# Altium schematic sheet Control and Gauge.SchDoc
size 431 x 279 mm; Date: Not shown in title block; ApprovedBy: Not shown in title block; CheckedBy: Not shown in title block; Author: Not shown in title block; CompanyName: Not shown in title block; Engineer: Not shown in title block; Organization: Not shown in title block; Address1: Not shown in title block; Address2: Not shown in title block; Address3: Not shown in title block; Address4: Not shown in title block; DocumentNumber: 1; Revision: Use project parameter SCH_Rev; SheetNumber: 2; SheetTotal: 3; PageSetup: Record=PageOptions¦CenterHorizontal=True¦CenterVertical=True¦PrintScale=1.00¦XCorrection=1.00¦YCorrection=1.00¦PrintKind=0¦BorderSize=5000000¦LeftOffset=0¦BottomOffset=0¦Orientation=2¦PaperLength=1000¦PaperWidth=1000¦Scale=100¦PaperSource=15¦PrintQuality=600¦MediaType=1¦DitherType=10¦PaperKind=Letter¦PrintScaleMode=1
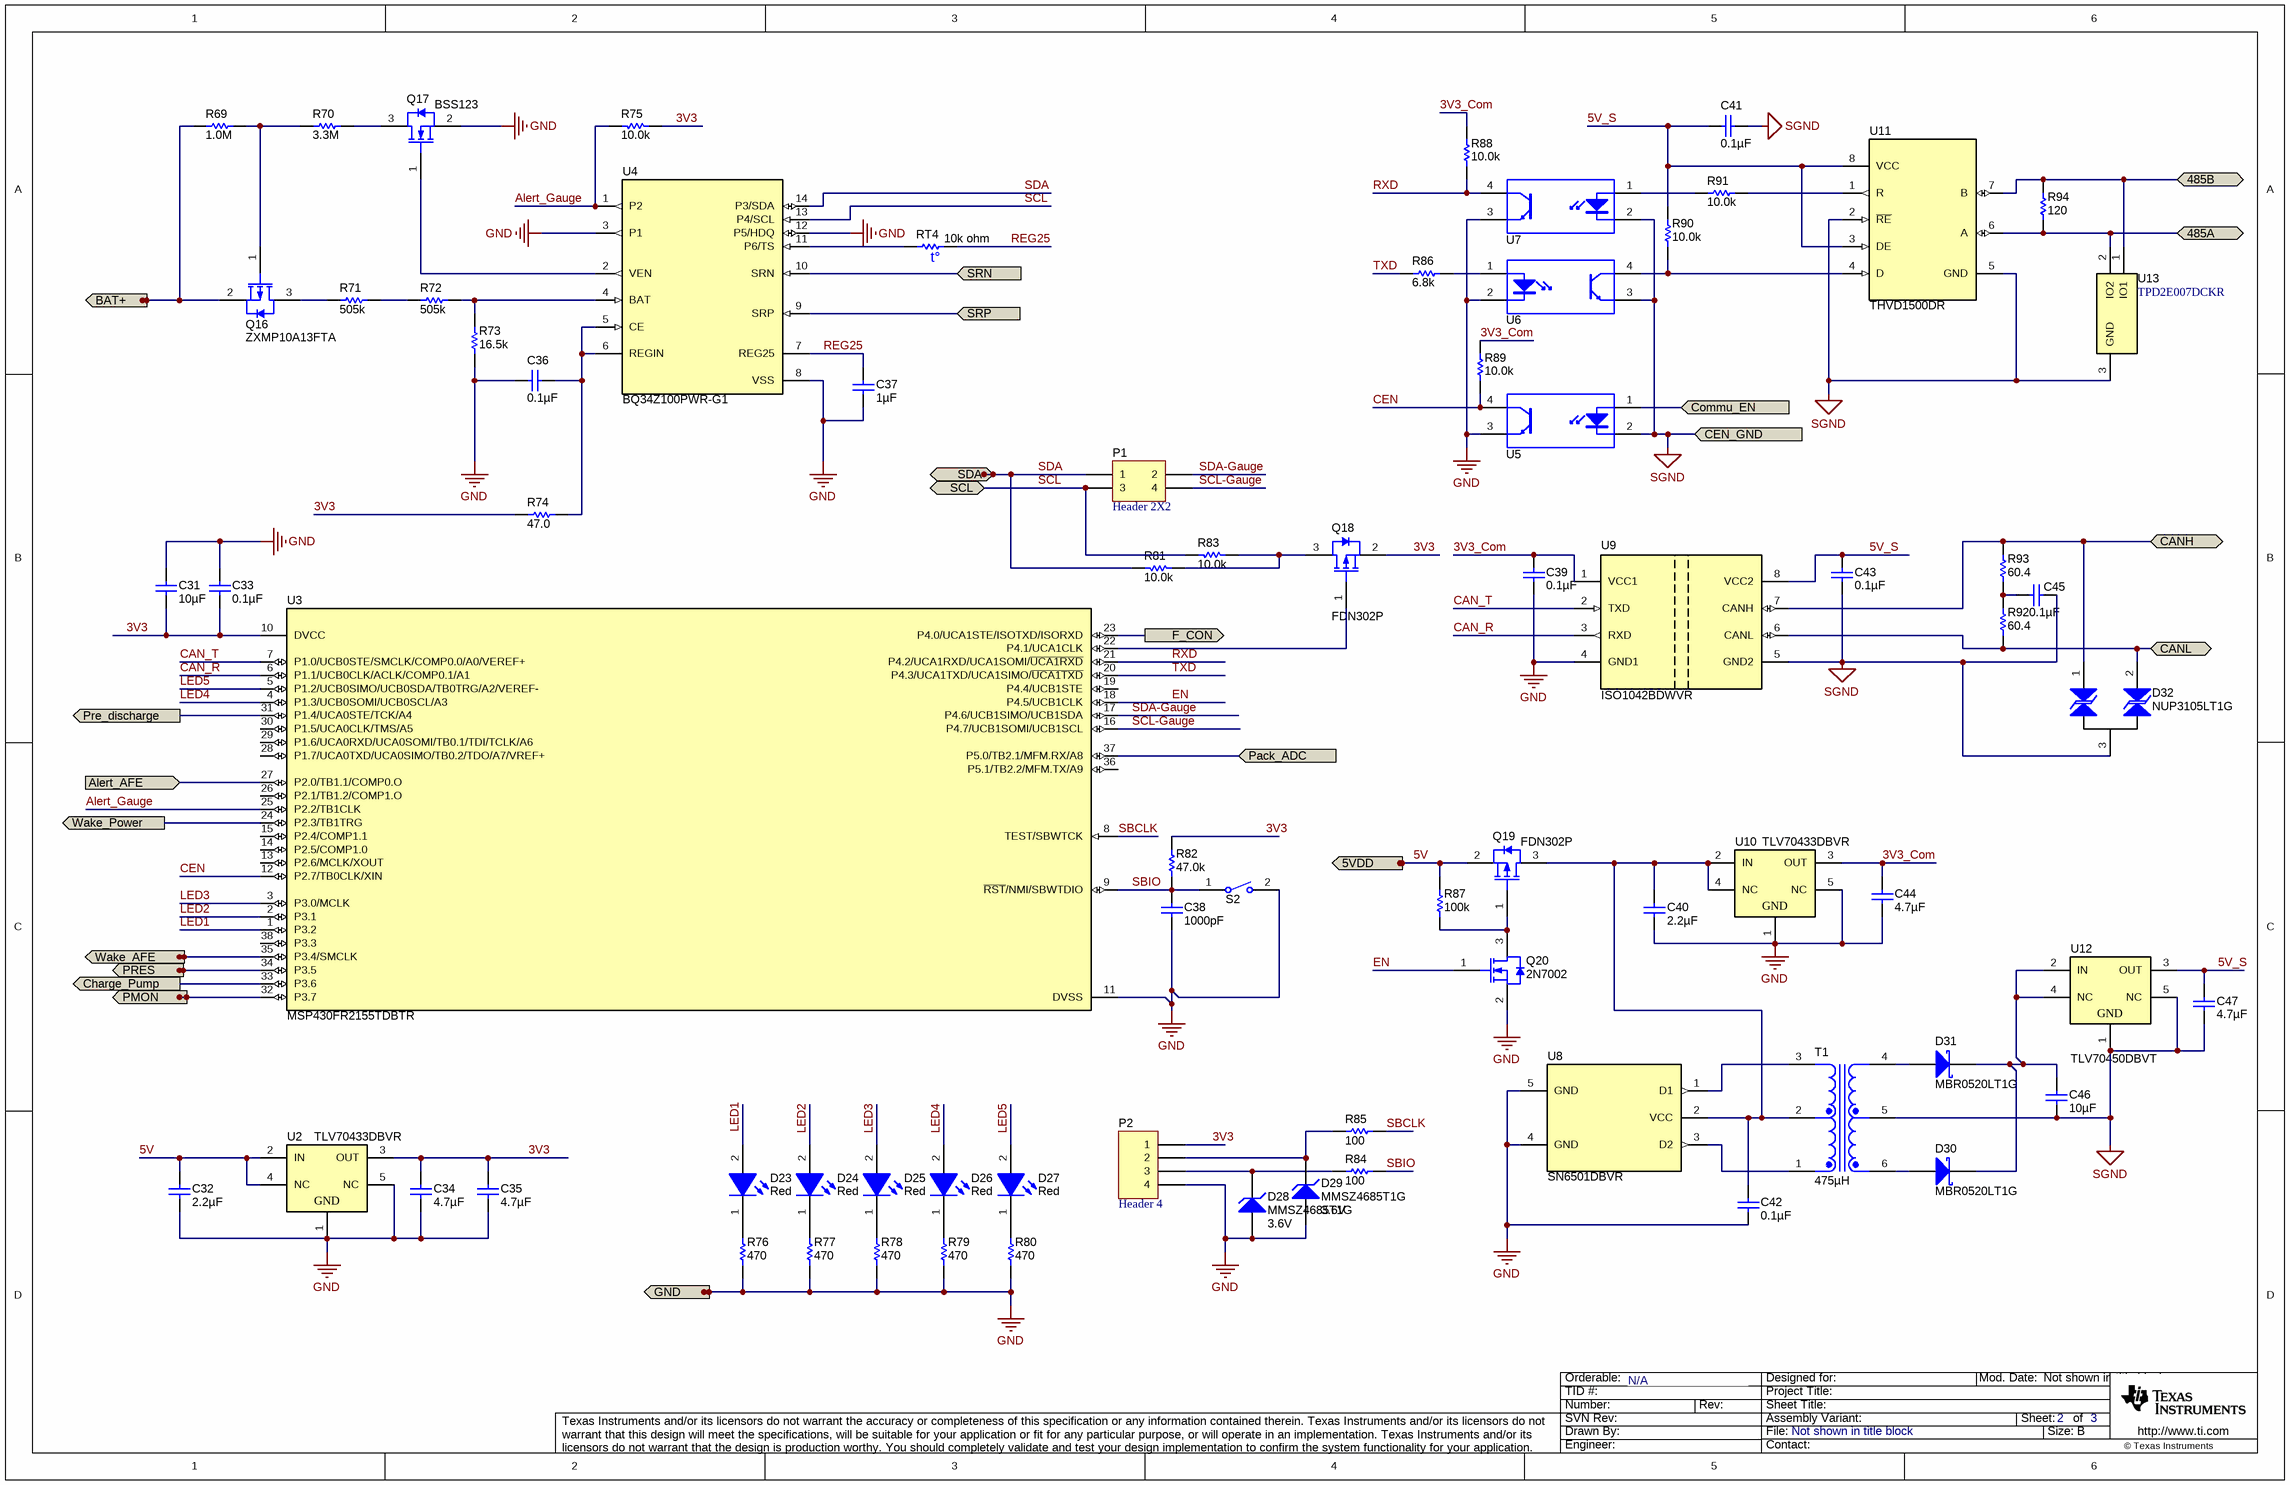
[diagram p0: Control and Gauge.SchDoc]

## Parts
C31  ValueDisplayed: 10µF  [0805_HV]  (hidden comment: CL21B106KOQNNNE)
C32  ValueDisplayed: 2.2µF  [0603]  (hidden comment: GRM188R71A225KE15D)
C33  ValueDisplayed: 0.1µF  [0603]  (hidden comment: GRM188R71C104KA01D)
C34  ValueDisplayed: 4.7µF  [0603]  (hidden comment: GRM188R61C475KAAJ)
C35  ValueDisplayed: 4.7µF  [0603]  (hidden comment: GRM188R61C475KAAJ)
C36  ValueDisplayed: 0.1µF  [0603]  (hidden comment: GRM188R71H104KA93D)
C37  ValueDisplayed: 1µF  [0603]  (hidden comment: GRM188R71C105KE15D)
C38  ValueDisplayed: 1000pF  [0603S]  (hidden comment: GRM1885C1H102JA01D)
C39  ValueDisplayed: 0.1µF  [0603]  (hidden comment: GRM188R71C104KA01D)
C40  ValueDisplayed: 2.2µF  [0603]  (hidden comment: GRM188R71A225KE15D)
C41  ValueDisplayed: 0.1µF  [0603]  (hidden comment: GRM188R71H104KA93D)
C42  ValueDisplayed: 0.1µF  [0603]  (hidden comment: GRM188R71C104KA01D)
C43  ValueDisplayed: 0.1µF  [0603]  (hidden comment: GRM188R71H104KA93D)
C44  ValueDisplayed: 4.7µF  [0603]  (hidden comment: GRM188R61C475KAAJ)
C45  ValueDisplayed: 0.1µF  [0603S]  (hidden comment: GRM188R71H104KA93D)
C46  ValueDisplayed: 10µF  [0805_HV]  (hidden comment: CL21B106KOQNNNE)
C47  ValueDisplayed: 4.7µF  [0603]  (hidden comment: GRM188R61C475KAAJ)
D23  value Red  [WL-SMCW_RED]  (hidden comment: 150060RS75000)
D24  value Red  [WL-SMCW_RED]  (hidden comment: 150060RS75000)
D25  value Red  [WL-SMCW_RED]  (hidden comment: 150060RS75000)
D26  value Red  [WL-SMCW_RED]  (hidden comment: 150060RS75000)
D27  value Red  [WL-SMCW_RED]  (hidden comment: 150060RS75000)
D28  MMSZ4685T1G  value 3.6V  [SOD-123]
D29  MMSZ4685T1G  value 3.6V  [SOD-123]
D30  MBR0520LT1G  [SOD-123]
D31  MBR0520LT1G  [SOD-123]
D32  NUP3105LT1G  [SOT-23]
P1  Header 2X2  [HDR2X2]
P2  Header 4  [HDR1X4]
Q16  ZXMP10A13FTA  [SOT-23]
Q17  BSS123  [SOT-23]
Q18  FDN302P  [SOT-23]
Q19  FDN302P  [SOT-23]
Q20  2N7002  [SOT-23]
R69  ValueDisplayed: 1.0M  [0603]  (hidden comment: CRCW06031M00JNEA)
R70  ValueDisplayed: 3.3M  [0603]  (hidden comment: CRCW06033M30JNEA)
R71  ValueDisplayed: 505k  [0603]  (hidden comment: RT0603BRD07505KL)
R72  ValueDisplayed: 505k  [0603]  (hidden comment: RT0603BRD07505KL)
R73  ValueDisplayed: 16.5k  [0603]  (hidden comment: RT0603BRD0716K5L)
R74  ValueDisplayed: 47.0  [0603]  (hidden comment: RC0603FR-0747RL)
R75  ValueDisplayed: 10.0k  [0603]  (hidden comment: CRCW060310K0FKEA)
R76  ValueDisplayed: 470  [0603]  (hidden comment: RC0603FR-07470RL)
R77  ValueDisplayed: 470  [0603]  (hidden comment: RC0603FR-07470RL)
R78  ValueDisplayed: 470  [0603]  (hidden comment: RC0603FR-07470RL)
R79  ValueDisplayed: 470  [0603]  (hidden comment: RC0603FR-07470RL)
R80  ValueDisplayed: 470  [0603]  (hidden comment: RC0603FR-07470RL)
R81  ValueDisplayed: 10.0k  [0603]  (hidden comment: CRCW060310K0FKEA)
R82  ValueDisplayed: 47.0k  [0603]  (hidden comment: RC0603FR-0747KL)
R83  ValueDisplayed: 10.0k  [0603]  (hidden comment: CRCW060310K0FKEA)
R84  ValueDisplayed: 100  [0603]  (hidden comment: CRCW0603100RFKEA)
R85  ValueDisplayed: 100  [0603]  (hidden comment: CRCW0603100RFKEA)
R86  ValueDisplayed: 6.8k  [0603]  (hidden comment: CRCW06036K80JNEA)
R87  ValueDisplayed: 100k  [0603]  (hidden comment: CRCW0603100KFKEA)
R88  ValueDisplayed: 10.0k  [0603]  (hidden comment: CRCW060310K0FKEA)
R89  ValueDisplayed: 10.0k  [0603]  (hidden comment: CRCW060310K0FKEA)
R90  ValueDisplayed: 10.0k  [0603]  (hidden comment: CRCW060310K0FKEA)
R91  ValueDisplayed: 10.0k  [0603S]  (hidden comment: CRCW060310K0FKEA)
R92  ValueDisplayed: 60.4  [0603S]  (hidden comment: RC0603FR-0760R4L)
R93  ValueDisplayed: 60.4  [0603S]  (hidden comment: RC0603FR-0760R4L)
R94  ValueDisplayed: 120  [0603]  (hidden comment: RC0603FR-07120RL)
RT4  value 10k ohm  [NTCALUG03]  (hidden comment: NTCALUG03A103G)
S2  RS-032G05A3-SM RT  [SW_RS-032G05A3-SM]  (value not drawn)
T1  ValueDisplayed: 475µH  [Wurth_760390012]  (hidden comment: 760390012)
U2  TLV70433DBVR  [DBV0005A_N]
U3  MSP430FR2155TDBTR  [DBT0038A_N]
U4  BQ34Z100PWR-G1  [PW0014A_N]
U5  TLP293(GB-TPL,E  [SO4]  (value not drawn)
U6  TLP293(GB-TPL,E  [SO4]  (value not drawn)
U7  TLP293(GB-TPL,E  [SO4]  (value not drawn)
U8  SN6501DBVR  [DBV0005A_N]
U9  ISO1042BDWVR  [DWV0008A]
U10  TLV70433DBVR  [DBV0005A_N]
U11  THVD1500DR  [D0008A_N]
U12  TLV70450DBVT  [DBV0005A_N]
U13  TPD2E007DCKR  [DCK0003A_N]

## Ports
5VDD, 485A (bidir), 485B (bidir), Alert_AFE (in), BAT+ (in), CANH (bidir), CANL (bidir), CEN_GND (in), Charge_Pump (out), Commu_EN (in), F_CON (out), GND, Pack_ADC (in), PMON (out), Pre_discharge (out), PRES (out), SCL (bidir), SDA (bidir), SRN (in), SRP (in), Wake_AFE (out), Wake_Power (out)

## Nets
GND: C31.1 C32.2 C33.1 C34.2 C35.2 C36.2 C37.2 C38.2 C39.1 C40.2 C42.2 C44.2 D28.2(A) D29.2(A) P2.4 Q17.2(S) Q20.2(S) R73.1 R76.1 R77.1 R78.1 R79.1 R80.1 S2.2 U2.1(GND) U2.5(NC) U3.11(DVSS) U4.3(P1) U4.8(VSS) U4.12(P5/HDQ) U5.3(E) U6.2(K) U7.3(E) U8.4(GND) U8.5(GND) U9.4(GND1) U10.1(GND) U10.5(NC) ; port GND
SGND: C41.2 C43.2 C45.1 C46.2 C47.2 D32.3 T1.5 U5.2(K) U6.3(E) U7.2(K) U9.5(GND2) U11.2(~{RE}) U11.5(GND) U12.1(GND) U12.5(NC) U13.3(GND) ; port CEN_GND
3V3: C31.2 C33.2 C34.1 C35.1 P2.1 Q18.2(S) R74.1 R75.1 R82.2 U2.3(OUT) U3.10(DVCC)
3V3_Com: C39.2 C44.1 R88.2 R89.2 U9.1(VCC1) U10.3(OUT)
5V: C32.1 Q19.2(S) R87.1 U2.2(IN) U2.4(NC) ; port 5VDD
5V_S: C41.1 C43.1 C47.1 R90.2 U9.8(VCC2) U11.3(DE) U11.8(VCC) U12.3(OUT)
485A: R94.2 U11.6(A) U13.2(IO2) ; port 485A
485B: R94.1 U11.7(B) U13.1(IO1) ; port 485B
Alert_AFE: U3.27(P2.0/TB1.1/COMP0.O) ; port Alert_AFE
Alert_Gauge: R75.2 U3.25(P2.2/TB1CLK) U4.1(P2)
BAT+: Q16.2(S) R69.1 ; port BAT+
CAN_R: U3.6(P1.1/UCB0CLK/ACLK/COMP0.1/A1) U9.3(RXD)
CAN_T: U3.7(P1.0/UCB0STE/SMCLK/COMP0.0/A0/VEREF+) U9.2(TXD)
CANH: D32.1 R93.1 U9.7(CANH) ; port CANH
CANL: D32.2 R92.2 U9.6(CANL) ; port CANL
CEN: R89.1 U3.12(P2.7/TB0CLK/XIN) U5.4(C)
Charge_Pump: U3.33(P3.6) ; port Charge_Pump
Commu_EN: U5.1(A) ; port Commu_EN
EN: Q20.1(G) U3.18(P4.5/UCB1CLK)
F_CON: U3.23(P4.0/UCA1STE/ISOTXD/ISORXD) ; port F_CON
LED1: D23.2(A) U3.1(P3.2)
LED2: D24.2(A) U3.2(P3.1)
LED3: D25.2(A) U3.3(P3.0/MCLK)
LED4: D26.2(A) U3.4(P1.3/UCB0SOMI/UCB0SCL/A3)
LED5: D27.2(A) U3.5(P1.2/UCB0SIMO/UCB0SDA/TB0TRG/A2/VEREF-)
Pack_ADC: U3.37(P5.0/TB2.1/MFM.RX/A8) ; port Pack_ADC
PMON: U3.32(P3.7) ; port PMON
Pre_discharge: U3.31(P1.4/UCA0STE/TCK/A4) ; port Pre_discharge
PRES: U3.34(P3.5) ; port PRES
REG25: C37.1 RT4.2 U4.7(REG25)
RXD: R88.1 U3.21(P4.2/UCA1RXD/UCA1SOMI/~{UCA1RXD}) U7.4(C)
SBCLK: R85.1 U3.8(TEST/SBWTCK)
SBIO: C38.1 R82.1 R84.1 S2.1 U3.9(~{RST}/NMI/SBWTDIO)
SCL: P1.3 R83.2 U4.13(P4/SCL) ; port SCL
SCL-Gauge: P1.4 U3.16(P4.7/UCB1SOMI/UCB1SCL)
SDA: P1.1 R81.2 U4.14(P3/SDA) ; port SDA
SDA-Gauge: P1.2 U3.17(P4.6/UCB1SIMO/UCB1SDA)
SRN: U4.10(SRN) ; port SRN
SRP: U4.9(SRP) ; port SRP
TXD: R86.2 U3.20(P4.3/UCA1TXD/UCA1SIMO/~{UCA1TXD})
Wake_AFE: U3.35(P3.4/SMCLK) ; port Wake_AFE
Wake_Power: U3.24(P2.3/TB1TRG) ; port Wake_Power
NetC36_1: C36.1 R74.2 U4.5(CE) U4.6(REGIN)
NetC40_1: C40.1 C42.1 Q19.3(D) T1.2 U8.2(VCC) U10.2(IN) U10.4(NC)
NetC45_2: C45.2 R92.1 R93.2
NetC46_1: C46.1 D30.1(K) D31.1(K) U12.2(IN) U12.4(NC)
NetD23_1: D23.1(K) R76.2
NetD24_1: D24.1(K) R77.2
NetD25_1: D25.1(K) R78.2
NetD26_1: D26.1(K) R79.2
NetD27_1: D27.1(K) R80.2
NetD28_1: D28.1(K) P2.3 R84.2
NetD29_1: D29.1(K) P2.2 R85.2
NetD30_2: D30.2(A) T1.6
NetD31_2: D31.2(A) T1.4
NetQ16_1: Q16.1(G) R69.2 R70.1
NetQ16_3: Q16.3(D) R71.1
NetQ17_1: Q17.1(G) U4.2(VEN)
NetQ17_3: Q17.3(D) R70.2
NetQ18_1: Q18.1(G) U3.22(P4.1/UCA1CLK)
NetQ18_3: Q18.3(D) R81.1 R83.1
NetQ19_1: Q19.1(G) Q20.3(D) R87.2
NetR71_2: R71.2 R72.1
NetR72_2: R72.2 R73.2 U4.4(BAT)
NetR86_1: R86.1 U6.1(A)
NetR90_1: R90.1 U6.4(C) U11.4(D)
NetR91_1: R91.1 U7.1(A)
NetR91_2: R91.2 U11.1(R)
NetRT4_1: RT4.1 U4.11(P6/TS)
NetT1_1: T1.1 U8.3(D2)
NetT1_3: T1.3 U8.1(D1)

Not connected (* = marked no-connect by the designer): U3 13(P2.6/MCLK/XOUT) 14(P2.5/COMP1.0) 15(P2.4/COMP1.1) 19(P4.4/UCB1STE) 26(P2.1/TB1.2/COMP1.O) 28(P1.7/UCA0TXD/UCA0SIMO/TB0.2/TDO/A7/VREF+) 29(P1.6/UCA0RXD/UCA0SOMI/TB0.1/TDI/TCLK/A6) 30(P1.5/UCA0CLK/TMS/A5) 36(P5.1/TB2.2/MFM.TX/A9) 38(P3.3)

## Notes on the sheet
- N/A

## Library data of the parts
C31 C46 = CL21B106KOQNNNE: CAP, CERM, 10 µF, 16 V,+/- 10%, X7R, 0805; Manufacturer: Samsung Electro-Mechanics; Polarized: N; CompType: Capacitor; Value: 10uF; U/M: EA; Cap_F: 0.00001; Tolerance_%: 10; VDC_V: 16; Value2: 16V; TaMin_C: -55; TaMax_C: 125; Cap_Case: 0805; SizeArea_mm2: 2.5; SizeAreaWB_mm2: 6.75; SizeX_mm: 2; SizeY_mm: 1.25; SizeZ_mm: 1.45; AEC Category: Q200; Green_Lifecycle: Active; Green_REACh: Passed
C32 C40 = GRM188R71A225KE15D: CAP, CERM, 2.2 µF, 10 V,+/- 10%, X7R, 0603; Manufacturer: MuRata; Polarized: N; CompType: Capacitor; Value: 2.2uF; U/M: EA; Cap_F: 0.0000022; Tolerance_%: 10; ESR_ohm: 0.009; Value1: 0.009 ohm; Value2: 10V; TaMin_C: -55; TaMax_C: 125; SizeArea_mm2: 1.28; SizeAreaWB_mm2: 4.68; SizeX_mm: 1.6; SizeY_mm: 0.8; SizeZ_mm: 1; AEC Category: Q200; Green_Lifecycle: Active; Green_REACh: Passed
C33 C39 C42 = GRM188R71C104KA01D: CAP, CERM, 0.1 µF, 16 V,+/- 10%, X7R, 0603; Manufacturer: MuRata; Polarized: N; CompType: Capacitor; Value: 0.1uF; U/M: EA; Cap_F: 0.0000001; Tolerance_%: 10; VDC_V: 16; Value2: 16V; TaMin_C: -55; TaMax_C: 125; SizeArea_mm2: 1.28; SizeAreaWB_mm2: 4.68; SizeX_mm: 1.6; SizeY_mm: 0.8; SizeZ_mm: 1; AEC Category: Q200; Green_Lifecycle: Active; Green_REACh: Passed
C34 C35 C44 C47 = GRM188R61C475KAAJ: CAP, CERM, 4.7 µF, 16 V,+/- 10%, X5R, 0603; Manufacturer: MuRata; Polarized: N; CompType: Capacitor; Value: 4.7uF; U/M: EA; Cap_F: 0.0000047; Tolerance_%: 10; VDC_V: 16; Value2: 16V; TaMin_C: -55; TaMax_C: 85; SizeArea_mm2: 1.28; SizeAreaWB_mm2: 4.68; SizeX_mm: 1.6; SizeY_mm: 0.8; SizeZ_mm: 1; AEC Category: Q200; Green_Lifecycle: Active; Green_REACh: Passed
C36 C41 C43 = GRM188R71H104KA93D: CAP, CERM, 0.1 µF, 50 V,+/- 10%, X7R, 0603; Manufacturer: MuRata; Polarized: N; CompType: Capacitor; Value: 0.1uF; U/M: EA; Cap_F: 0.0000001; Tolerance_%: 10; VDC_V: 50; Value2: 50V; TaMin_C: -55; TaMax_C: 125; SizeArea_mm2: 1.28; SizeAreaWB_mm2: 4.68; SizeX_mm: 1.6; SizeY_mm: 0.8; SizeZ_mm: 1; AEC Category: Q200; Green_Lifecycle: Active; Green_REACh: Passed
C37 = GRM188R71C105KE15D: CAP, CERM, 1 µF, 16 V,+/- 10%, X7R, 0603; Manufacturer: MuRata; Polarized: N; CompType: Capacitor; Value: 1uF; U/M: EA; Cap_F: 0.000001; Tolerance_%: 10; VDC_V: 16; Value2: 16V; TaMin_C: -55; TaMax_C: 125; SizeArea_mm2: 1.28; SizeAreaWB_mm2: 4.68; SizeX_mm: 1.6; SizeY_mm: 0.8; SizeZ_mm: 1; AEC Category: Q200
C38 = GRM1885C1H102JA01D: CAP, CERM, 1000 pF, 50 V,+/- 5%, C0G/NP0, 0603; Manufacturer: MuRata; Polarized: N; CompType: Capacitor; Value: 1000pF; U/M: EA; Cap_F: 0.000000001; Tolerance_%: 5; VDC_V: 50; Value2: 50V; TaMin_C: -55; TaMax_C: 125; Cap_Case: 0603; SizeArea_mm2: 1.28; SizeAreaWB_mm2: 4.68; SizeX_mm: 1.6; SizeY_mm: 0.8; SizeZ_mm: 1; AEC Category: Q200; Green_Lifecycle: Active; Green_REACh: Passed
C45 = GRM188R71H104KA93D: CAP, CERM, 0.1 µF, 50 V,+/- 10%, X7R, 0603; Manufacturer: MuRata; Polarized: N; CompType: Capacitor; Value: 0.1uF; U/M: EA; Cap_F: 0.0000001; Tolerance_%: 10; VDC_V: 50; Value2: 50V; TaMin_C: -55; TaMax_C: 125; Cap_Case: 0603; SizeArea_mm2: 1.28; SizeAreaWB_mm2: 4.68; SizeX_mm: 1.6; SizeY_mm: 0.8; SizeZ_mm: 1; AEC Category: Q200; Green_Lifecycle: Active; Green_REACh: Passed
D23-D27 = 150060RS75000: LED, Red, SMD; Manufacturer: Wurth Elektronik; Type: AlInGaP; Vf_V: 2; Value2: 2V; Io_A: 0.03; Vr_V: 5; Tjmax_C: 85; Power_TotalModule: 0.072; Value1: 0.072W; Angle: 140; U/M: EA; Green_Lifecycle: Active; Green_REACh: Passed
D28 D29 = MMSZ4685T1G: Diode, Zener, 3.6 V, 500 mW, SOD-123; Manufacturer: ON Semiconductor; SymbolCreator: a0412235; U/M: EA; Power_W: 0.5; Vz_V: 3.6; Value1: 0.5W; RJA_CperW: 340; SizeAreaWB_mm2: 13.095; SizeArea_mm2: 6.545; SizeX_mm: 3.85; SizeY_mm: 1.7; SizeZ_mm: 1.35; AEC Category: Q101; Green_Lifecycle: Active; Green_REACh: Passed
D30 D31 = MBR0520LT1G: Diode, Schottky, 20 V, 0.5 A, SOD-123; Manufacturer: ON Semiconductor; U/M: EA; Vf_V: 0.385; Value: 20V; Value1: 0.5A; Value2: 0.385V; Io_A: 0.5; Vr_V: 20; TJmax_C: 125; RJC_CperW: 150; SizeAreaWB_mm2: 13.095; SizeArea_mm2: 6.545; SizeX_mm: 3.85; SizeY_mm: 1.7; SizeZ_mm: 1.35; AEC Category: Q101; Green_Lifecycle: Active; Green_REACh: Passed
D32 = NUP2105LT1G: Diode, TVS, Bi, 24 V, SOT-23; Manufacturer: ON Semiconductor; SymbolCreator: a0411947; Value: 24V; U/M: EA; Power_W: 0.35; Vr_V: 24; Value1: 0.35W; SizeAreaWB_mm2: 14; SizeArea_mm2: 7.5; SizeX_mm: 2.5; SizeY_mm: 3; SizeZ_mm: 1.1; AEC Category: Q101
P1 = Header 2X2: Header, 2-Pin, Dual row
P2 = Header 4: Header, 4-Pin
Q16 = ZXMP10A13FTA: MOSFET, P-CH, -100 V, -0.6 A, SOT-23; Manufacturer: Diodes Inc.; Alternate Manufacturer: None; U/M: EA; ChType: P; Value: -100V; Value1: 1 ohm; Rdson45_ohm: 1; Value2: 3.5 nC; QgTyp_nC: 3.5; Vgs_V: -4; SizeAreaWB_mm2: 14; SizeArea_mm2: 7.5; SizeX_mm: 2.5; SizeY_mm: 3; SizeZ_mm: 1.1; AEC Category: Q101; Green_Lifecycle: Active; Green_REACh: Passed
Q17 = BSS123: MOSFET, N-CH, 100 V, 0.17 A, SOT-23; Manufacturer: Fairchild Semiconductor; Alternate Manufacturer: None; U/M: EA; ChType: N; Value: 100V; VdsMax_V: 100; Value1: 10 ohm; Rdson45_ohm: 10; Value2: 1.8 nC; QgTyp_nC: 1.8; Vgs_V: 20; IdsMax_A: 0.17; SizeAreaWB_mm2: 14; SizeArea_mm2: 7.5; SizeX_mm: 2.5; SizeY_mm: 3; SizeZ_mm: 1.1; AEC Category: Q101; Green_Lifecycle: Active; Green_REACh: Passed
Q18 Q19 = FDN302P: MOSFET, P-CH, -20 V, -2.4 A, SOT-23; Manufacturer: Fairchild Semiconductor; Alternate Manufacturer: None; U/M: EA; ChType: P; Value: -20V; Value1: 0.055 ohm; Rdson45_ohm: 0.055; Value2: 9 nC; QgTyp_nC: 9; Vgs_V: -12; SizeAreaWB_mm2: 14; SizeArea_mm2: 7.5; SizeX_mm: 2.5; SizeY_mm: 3; SizeZ_mm: 1.1; AEC Category: Q101; Green_Lifecycle: Active; Green_REACh: Passed
Q20 = 2N7002: MOSFET, N-CH, 60 V, 115 A, SOT-23; Manufacturer: Fairchild Semiconductor; Alternate Manufacturer: None; U/M: EA; ChType: N; Value: 60V; VdsMax_V: 60; Value1: ? ohm; Value2: ? nC; Vgs_V: 20; IdsMax_A: 115; SizeAreaWB_mm2: 14; SizeArea_mm2: 7.5; SizeX_mm: 2.5; SizeY_mm: 3; SizeZ_mm: 1.1; AEC Category: Q101; Green_Lifecycle: Active; Green_REACh: Passed
R69 = CRCW06031M00JNEA: RES, 1.0 M, 5%, 0.1 W, 0603; Manufacturer: Vishay-Dale; CompType: Resistor; Value: 1.0Meg; Res_ohm: 1000000; Value_Code: 1M00; Tolerance_%: 5; Power_W: 0.1; Value2: 0.1W; VDC_V: 75; TempCo: 200 ppm/C; SizeArea_mm2: 1.28; SizeX_mm: 1.6; SizeY_mm: 0.8; SizeZ_mm: 1; EIA_Code: E24; U/M: EA; AEC Category: Q200; Green_Lifecycle: Active; Green_REACh: Passed
R70 = CRCW06033M30JNEA: RES, 3.3 M, 5%, 0.1 W, 0603; Manufacturer: Vishay-Dale; CompType: Resistor; Value: 3.3Meg; Res_ohm: 3300000; Value_Code: 3M30; Tolerance_%: 5; Power_W: 0.1; Value2: 0.1W; VDC_V: 75; TempCo: 200 ppm/C; SizeArea_mm2: 1.28; SizeX_mm: 1.6; SizeY_mm: 0.8; SizeZ_mm: 1; EIA_Code: E24; U/M: EA; AEC Category: Q200; Green_Lifecycle: Active; Green_REACh: Passed
R71 R72 = RT0603BRD07505KL: RES, 505 k, 0.1%, 0.1 W, 0603; Manufacturer: Yageo America; CompType: Resistor; Value: 505k; Res_ohm: 505000; Tolerance_%: 0.1; Value2: 0.1W; VDC_V: 75; TempCo: 25 ppm/C; SizeArea_mm2: 1.28; SizeX_mm: 1.6; SizeY_mm: 0.8; SizeZ_mm: 1; EIA_Code: E192; U/M: EA; AEC Category: Q200
R73 = RT0603BRD0716K5L: RES, 16.5 k, 0.1%, 0.1 W, 0603; Manufacturer: Yageo America; CompType: Resistor; Value: 16.5k; Res_ohm: 16500; Value_Code: 16k5; Tolerance_%: 0.1; Value2: 0.1W; VDC_V: 75; TempCo: 25 ppm/C; SizeArea_mm2: 1.28; SizeX_mm: 1.6; SizeY_mm: 0.8; SizeZ_mm: 1; EIA_Code: E192; U/M: EA; AEC Category: Q200
R74 = RC0603FR-0747RL: RES, 47.0, 1%, 0.1 W, 0603; Manufacturer: Yageo America; CompType: Resistor; Value: 47.0; Res_ohm: 47; Value_Code: 47R0; Tolerance_%: 1; Power_W: 0.1; Value2: 0.1W; VDC_V: 150; TempCo: 200 ppm/C; SizeArea_mm2: 1.28; SizeX_mm: 1.6; SizeY_mm: 0.8; U/M: EA; AEC Category: Q200; Green_Lifecycle: Active; Green_REACh: Passed
R75 R81 R83 R88-R91 = CRCW060310K0FKEA: RES, 10.0 k, 1%, 0.1 W, 0603; Manufacturer: Vishay-Dale; CompType: Resistor; Value: 10.0k; Res_ohm: 10000; Value_Code: 10k0; Tolerance_%: 1; Power_W: 0.1; Value2: 0.1W; VDC_V: 75; TempCo: 100 ppm/C; SizeArea_mm2: 1.28; SizeX_mm: 1.6; SizeY_mm: 0.8; EIA_Code: E96; U/M: EA; AEC Category: Q200; Green_Lifecycle: Active; Green_REACh: Passed
R76-R80 = RC0603FR-07470RL: RES, 470, 1%, 0.1 W, 0603; Manufacturer: Yageo America; CompType: Resistor; Value: 470; Value_Code: 470R; Tolerance_%: 1; Power_W: 0.1; Value2: 0.1W; VDC_V: 150; TempCo: 200 ppm/C; SizeArea_mm2: 1.28; SizeX_mm: 1.6; SizeY_mm: 0.8; U/M: EA; AEC Category: Q200; Green_Lifecycle: Active; Green_REACh: Passed
R82 = RC0603FR-0747KL: RES, 47.0 k, 1%, 0.1 W, 0603; Manufacturer: Yageo America; CompType: Resistor; Value: 47.0k; Res_ohm: 47000; Value_Code: 47k0; Tolerance_%: 1; Power_W: 0.1; Value2: 0.1W; VDC_V: 150; TempCo: 200 ppm/C; SizeArea_mm2: 1.28; SizeX_mm: 1.6; SizeY_mm: 0.8; U/M: EA; AEC Category: Q200; Green_Lifecycle: Active; Green_REACh: Passed
R84 R85 = CRCW0603100RFKEA: RES, 100, 1%, 0.1 W, 0603; Manufacturer: Vishay-Dale; CompType: Resistor; Value: 100; Value_Code: 100R; Tolerance_%: 1; Power_W: 0.1; Value2: 0.1W; VDC_V: 75; TempCo: 100 ppm/C; SizeArea_mm2: 1.28; SizeX_mm: 1.6; SizeY_mm: 0.8; EIA_Code: E96; U/M: EA; AEC Category: Q200; Green_Lifecycle: Active; Green_REACh: Passed
R86 = CRCW06036K80JNEA: RES, 6.8 k, 5%, 0.1 W, 0603; Manufacturer: Vishay-Dale; CompType: Resistor; Value: 6.8k; Res_ohm: 6800; Value_Code: 6k80; Tolerance_%: 5; Power_W: 0.1; Value2: 0.1W; VDC_V: 75; TempCo: 200 ppm/C; SizeArea_mm2: 1.28; SizeX_mm: 1.6; SizeY_mm: 0.8; SizeZ_mm: 1; EIA_Code: E24; U/M: EA; AEC Category: Q200
R87 = CRCW0603100KFKEA: RES, 100 k, 1%, 0.1 W, 0603; Manufacturer: Vishay-Dale; CompType: Resistor; Value: 100k; Res_ohm: 100000; Tolerance_%: 1; Power_W: 0.1; Value2: 0.1W; VDC_V: 75; TempCo: 100 ppm/C; SizeArea_mm2: 1.28; SizeX_mm: 1.6; SizeY_mm: 0.8; EIA_Code: E96; U/M: EA; AEC Category: Q200; Green_Lifecycle: Active; Green_REACh: Passed
R92 R93 = RC0603FR-0760R4L: RES, 60.4, 1%, 0.1 W, 0603; Manufacturer: Yageo America; CompType: Resistor; Value: 60.4; Value_Code: 60R4; Tolerance_%: 1; Power_W: 0.1; Value2: 0.1W; VDC_V: 150; TempCo: 200 ppm/C; SizeArea_mm2: 1.28; SizeX_mm: 1.6; SizeY_mm: 0.8; EIA_Code: E96; U/M: EA; AEC Category: Q200
R94 = RC0603FR-07120RL: RES, 120, 1%, 0.1 W, 0603; Manufacturer: Yageo America; CompType: Resistor; Value: 120; Value_Code: 120R; Tolerance_%: 1; Power_W: 0.1; Value2: 0.1W; VDC_V: 150; TempCo: 200 ppm/C; SizeArea_mm2: 1.28; SizeX_mm: 1.6; SizeY_mm: 0.8; U/M: EA; AEC Category: Q200; Green_Lifecycle: Active; Green_REACh: Passed
RT4 = NTCALUG03A103G: Thermistor NTC, 10k ohm, 2%, NTC Thermistor, Mini Lug Sensor, Pitch 1.5mm; Manufacturer: Vishay-Bccomponents; Tolerance_%: 2; Power_W: 0.1; TaMin_C: -40; TaMax_C: 125; U/M: EA
S2 = RS-032G05A3-SM RT: Switch, Tactile, SPST-NO, 0.05A, 12V, SMD; Manufacturer: C&K Components; SymbolCreator: a0799628; VDC_V: 12; SwitchFunction: Off-Mom; PositionCount: 1; CurrentRating_mA: 50; Green_Lifecycle: Not Set; Green_REACh: Incomplete
T1 = 760390012: Transformer, 475 uH, SMT; Manufacturer: Wurth Elektronik; SymbolCreator: Altium; Value: 475uH; DCR_ohm: 0.31; Lp: 475; Ind_H: 0.000475; Ns1toNp: 1.1; Rsec1_ohm: 0.33; SizeAreaWB_mm2: 105.1965; SizeArea_mm2: 67.6365; SizeX_mm: 10.05; SizeY_mm: 6.73; SizeZ_mm: 4.19
U2 U10 = TLV70433DBVR: Single Output LDO, 150 mA, Fixed 3.3 V Output, 2.5 to 24 V Input, with Ultra-Low IQ, 5-pin SOT-23 (DBV), -40 to 125 degC, Green (RoHS & no Sb/Br); Manufacturer: Texas Instruments; Alternate PartNumber: Equivalent; Accuracy(%): 2; Fixed Output Options(V): 3.3; Iout(Max)(A): 0.15; Iq(Typ)(mA): 0.003; SubFamily: Single Channel LDO; Vdo(Typ)(mV): 400; Vin(Max)(V): 24; Vin(Min)(V): 2.5
U3 = CMP-0084060-1: 24MHz 105C ULP Microcontroller With 32 KB FRAM, 4 KB SRAM, 44 IO, 12-bit ADC, DBT0038A (TSSOP-38); Manufacturer: Texas Instruments; Rating: Catalog; SizeAreaWB_mm2: 98.28; SizeArea_mm2: 62.08; AEC Qualified: N; AEC Category: Q200; SizeZ_mm: 1.2; SizeY_mm: 9.7; CompType: IC; SizeX_mm: 6.4
U4 = CMP-0082025-1: Multi-Chemistry Impedance Track Standalone Fuel Gauge; Alternate PartNumber: BQ34Z100PW-G1; Alternate Manufacturer: Texas Instruments; SizeAreaWB_mm2: 58.8; SizeZ_mm: 1.2; SizeX_mm: 6.4; SizeY_mm: 5; SizeArea_mm2: 32; CompType: IC; AEC Qualified: N; AEC Category: Q200
U5-U7 = TLP293(GB-TPL,E: Optocoupler, 3.75 kV, 100-600% CTR, SMT; Manufacturer: Toshiba; CTR (Min): 100%; CTR (Max): 600%; Voltage_Isolation_Vrms: 3750V; SizeAreaWB_mm2: 41.4; SizeArea_mm2: 18.2; SizeX_mm: 7; SizeY_mm: 2.6; SizeZ_mm: 2.2
U8 = CMP-0065840-1: Low-Noise 350 mA, 410 kHz Transformer Driver, DBV0005A (SOT-23-5); Alternate PartNumber: SN6501DBVT; Alternate Manufacturer: Texas Instruments; Green_Lifecycle: Not Set; SizeAreaWB_mm2: 14.82; Green_REACh: Passed; U/M: EA; SizeZ_mm: 1.45; SizeX_mm: 2.8; SizeY_mm: 2.9; SizeArea_mm2: 8.12; CompType: IC
U9 = CMP-0077952-1: Reinforced Isolated CAN XCVRs with 70V Protection Voltage and CAN FD, DWV0008A (SOIC-8); Alternate Manufacturer: Texas Instruments; SizeAreaWB_mm2: 105.975; SizeZ_mm: 2.8; SizeX_mm: 11.5; SizeY_mm: 5.85; SizeArea_mm2: 67.275; CompType: IC; AEC Qualified: N; AEC Category: Q200
U11 = CMP-0013008-2: 250 kbps RS-485 Transceivers With +/-12-kV IEC ESD Protection, D0008A (SOIC-8); Manufacturer: Texas Instruments; SizeX_mm: 4.9; SizeY_mm: 6.2; CompType: IC; SizeZ_mm: 1.75; SizeArea_mm2: 30.38; SizeAreaWB_mm2: 56.58; U/M: EA
U12 = TLV70450DBVT: Single Output LDO, 150 mA, Fixed 5 V Output, 2.5 to 24 V Input, with Ultra-Low IQ, 5-pin SOT-23 (DBV), -40 to 125 degC, Green (RoHS & no Sb/Br); Manufacturer: Texas Instruments; Alternate PartNumber: Equivalent; Accuracy(%): 2; Fixed Output Options(V): 5; Iout(Max)(A): 0.15; Iq(Typ)(mA): 0.003; SubFamily: Single Channel LDO; Vdo(Typ)(mV): 400; Vin(Max)(V): 24; Vin(Min)(V): 2.5
U13 = TPD2E007DCKR: ESD Protection Array for AC Signal Data Interface, 2 Channels, -40 to +85 degC, 3-pin SC70 (DCK), Green (RoHS & no Sb/Br); Manufacturer: Texas Instruments; Alternate PartNumber: Equivalent; Breakdown Voltage(Min)(V): +/-14; IEC 61000-4-2 Air-Gap(+/- kV): 15; IEC 61000-4-2 Contact(+/- kV): 8; IO Leakage Current(nA): 50; SubFamily: ESD Solution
